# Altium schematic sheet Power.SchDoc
size A4; Organization: Altium Limited; Address1: L3, 12a Rodborough Rd; Address2: Frenchs Forest; Address3: NSW; Address4: Australia 2086
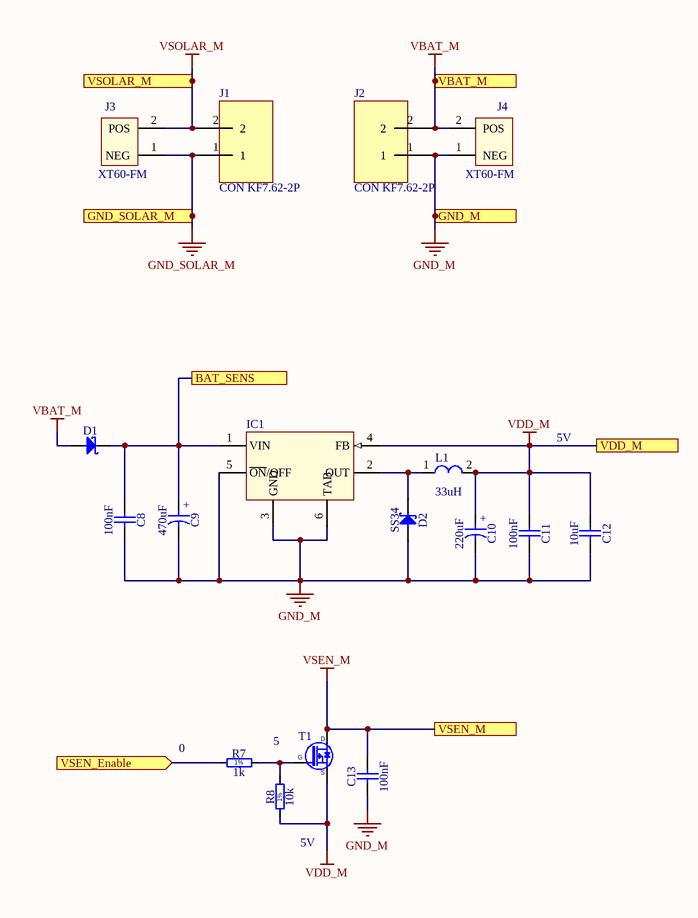
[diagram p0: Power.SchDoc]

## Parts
C8  100nF  [CAPC1608X87N]
C9  470uF  [CAPAE1030X1020N]
C10  220uF  [CAPMP6032X280N]
C11  100nF  [CAPC1608X87N]
C12  10uF  [CAPC2012X135N]
C13  100nF  [CAPC1608X87N]
D1  SS16  [DIOM5127X229N]  (value not drawn)
D2  SS34  [DIOM5127X229N]
IC1  LM2596  [TO263-5]  (value not drawn)
J1  CON KF7.62-2P  [CON KF7.62-2P]
J2  CON KF7.62-2P  [CON KF7.62-2P]
J3  XT60-FM  [XT60-FM]
J4  XT60-FM  [XT60-FM]
L1  33uH  [L_SMD]
R7  1k  [RESC1608X55N]
R8  10k  [RESC1608X55N]
T1  BSH203  [SOT95P230X110-3N]  (value not drawn)

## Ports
BAT_SENS, GND_M, GND_SOLAR_M, VBAT_M, VDD_M, VSEN_Enable (in), VSEN_M, VSOLAR_M

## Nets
GND_M: C8.2 C9.2 C10.2 C11.2 C12.2 C13.1 D2.2(A) IC1.3(GND) IC1.5(~{ON}/OFF) IC1.6(TAB) J2.1 J4.1(NEG) ; port GND_M
GND_SOLAR_M: J1.1 J3.1(NEG) ; port GND_SOLAR_M
VBAT_M: D1.2(A) J2.2 J4.2(POS) ; port VBAT_M
VDD_M: C10.1 C11.1 C12.1 IC1.4(FB) L1.2 R8.1 T1.2(S) ; port VDD_M
VSEN_M: C13.2 T1.3(D) ; port VSEN_M
VSOLAR_M: J1.2 J3.2(POS) ; port VSOLAR_M
BAT_SENS: C8.1 C9.1 D1.1(C) IC1.1(VIN) ; port BAT_SENS
VSEN_Enable: R7.1 ; port VSEN_Enable
NetD2_1: D2.1(C) IC1.2(OUT) L1.1
NetR7_2: R7.2 R8.2 T1.1(G)

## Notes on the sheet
- 5V
- 5
- (near R7) 0
- (near R8) 5V

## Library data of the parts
C8 C11 C13 = CC0603_100NF_50V_10%_X7R: Non-polarised capacitor; Part Description: SMD Multilayer Chip Ceramic Capacitor; Manufacturer: GENERIC; Manufacturer1 Part Number: 223858615649; Voltage: 50V; TC: X7R; Tolerance: ±10%; Table: Capacitors SMD
C9 = CAE1030-1020_470UF_25V_20%: Polarised capacitor; Part Description: Aluminum Electrolytic SMT Capacitor; Manufacturer: GENERIC; Manufacturer1 Part Number: EEEFK1E471AP; Voltage: 25V; Tolerance: ±20%; Table: Capacitors SMD
C10 = CTE6032-28_100UF_6.3V_10%_LESR0075: Polarised capacitor; Part Description: Low ESR 0R075 Solid Tantalum Chip Capacitor; Manufacturer: GENERIC; Manufacturer1 Part Number: TPSC107K006R0075; Value: 100uF; Voltage: 6.3V; Tolerance: ±10%; Table: Capacitors SMD
C12 = CC0805_10UF_16V_10%_X5R: Non-polarised capacitor; Part Description: SMD Multilayer Chip Ceramic Capacitor; Manufacturer: GENERIC; Manufacturer1 Part Number: C0805C106K4PAC; Voltage: 16V; TC: X5R; Tolerance: ±10%; Table: Capacitors SMD
D1 = SS16: Schottky Diode; Part Description: Surface Mount Schottky Barrier Rectifier; Manufacturer: VISHAY GENERAL SEMICONDUCTOR; Voltage: 60V; Power: 1A; Table: Diodes
D2 = SS16: Schottky Diode; Part Number: SS16; Part Description: Surface Mount Schottky Barrier Rectifier; Manufacturer: VISHAY GENERAL SEMICONDUCTOR; Voltage: 60V; Power: 1A; Table: Diodes
IC1 = LM2596-5V
J3 J4 = XT60-FM: MF: AMASS; MP: XT60-M
L1 = L_SMD 33uH
R7 = R0603_1K_1%_0.1W_100PPM: Resistor - 1%; Part Description: General Purpose Thick Film Chip Resistor; Manufacturer: GENERIC; Manufacturer1 Part Number: NRC06F1001TRF; Power: 0.1W; TC: ±100ppm/°C; Table: Resistors SMD
R8 = R0603_10K_1%_0.1W_100PPM: Resistor - 1%; Part Description: General Purpose Thick Film Chip Resistor; Manufacturer: GENERIC; Manufacturer1 Part Number: NRC06F1002TRF; Power: 0.1W; TC: ±100ppm/°C; Table: Resistors SMD
T1 = BSH203: P-CHANNEL MOSFET WITH DIODE; Part Description: -30V -470mA P-Channel Enhancement Mode MOS Transistor; Manufacturer: NXP SEMICONDUCTORS; Table: Transistors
